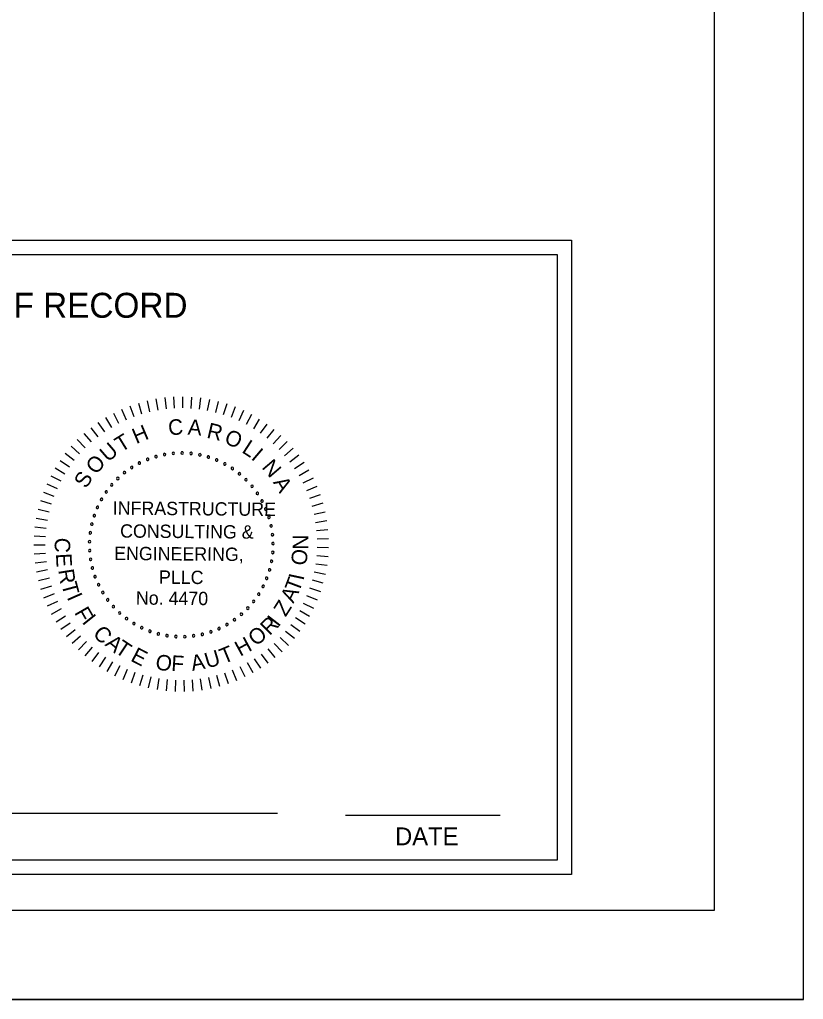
# Model space of a CAD drawing. Extents: x -1142 to 658, y -589 to 511.
# Drawn here: x 438.1 to 658.2, y -589.3 to -314.3 of the extents above; entities that cross this region are included whole.
import ezdxf

# ---------------------------------------------------------------- set-up
doc = ezdxf.new("R2010")
doc.units = 0
for name, color, linetype in [('BR_BORDER LINES', 7, 'Continuous'), ('BR_TEXT', 7, 'Continuous'), ('Default', 7, 'Continuous'), ('Level 31', 7, 'Continuous'), ('RD_SHT_IplotShp', 7, 'Continuous')]:
    doc.layers.add(name, color=color, linetype=linetype)

msp = doc.modelspace()

# ---------------------------------------------------------------- linework, layer by layer
at = {"layer": 'BR_BORDER LINES'}
for p, q in [((633.21, -564.26), (633.21, 485.67)), ((-1041.79, -564.26), (633.21, -564.26))]:
    msp.add_line(p, q, dxfattribs=at)
at = {"layer": 'BR_TEXT'}
for p, q in [((478.82, -420.42), (479.18, -423.58)), ((481.33, -420.21), (481.5, -423.39)), ((483.86, -420.16), (483.83, -423.34)), ((486.38, -420.26), (486.16, -423.44)), ((488.89, -420.51), (488.48, -423.67)), ((469.02, -422.76), (470.13, -425.74)), ((471.41, -421.95), (472.34, -425)), ((473.85, -421.29), (474.59, -424.39)), ((476.32, -420.78), (476.87, -423.91)), ((491.38, -420.92), (490.77, -424.05)), ((493.84, -421.48), (493.05, -424.56)), ((496.26, -422.19), (495.28, -425.22)), ((498.64, -423.04), (497.48, -426)), ((462.2, -426.04), (463.84, -428.77)), ((464.41, -424.81), (465.88, -427.63)), ((466.68, -423.71), (467.98, -426.62)), ((500.96, -424.04), (499.62, -426.92)), ((503.21, -425.17), (501.7, -427.97)), ((458.04, -428.89), (460, -431.4)), ((460.08, -427.4), (461.88, -430.02)), ((505.39, -426.45), (503.71, -429.15)), ((507.49, -427.85), (505.65, -430.44)), ((456.1, -430.5), (458.2, -432.88)), ((509.5, -429.38), (507.5, -431.85)), ((511.41, -431.02), (509.27, -433.37)), ((452.52, -434.06), (454.9, -436.17)), ((454.25, -432.22), (456.5, -434.48)), ((513.22, -432.78), (510.94, -435)), ((450.9, -436), (453.41, -437.96)), ((514.92, -434.65), (512.5, -436.72)), ((516.5, -436.62), (513.96, -438.54)), ((449.41, -438.03), (452.03, -439.84)), ((517.96, -438.68), (515.31, -440.44)), ((446.8, -442.35), (449.62, -443.82)), ((448.04, -440.15), (450.76, -441.79)), ((519.29, -440.83), (516.54, -442.42)), ((445.7, -444.62), (448.6, -445.92)), ((520.49, -443.05), (517.64, -444.47)), ((521.54, -445.34), (518.62, -446.59)), ((444.73, -446.95), (447.71, -448.07)), ((522.46, -447.69), (519.46, -448.76)), ((443.92, -449.34), (446.96, -450.28)), ((523.23, -450.09), (520.18, -450.98)), ((443.25, -451.78), (446.34, -452.52)), ((523.86, -452.54), (520.75, -453.24)), ((442.73, -454.25), (445.86, -454.8)), ((524.33, -455.02), (521.19, -455.53)), ((442.36, -456.74), (445.52, -457.11)), ((524.65, -457.52), (521.48, -457.84)), ((442.08, -461.78), (445.26, -461.76)), ((442.14, -459.26), (445.32, -459.43)), ((524.82, -460.04), (521.64, -460.16)), ((442.17, -464.3), (445.35, -464.09)), ((524.84, -462.57), (521.65, -462.49)), ((442.42, -466.82), (445.57, -466.41)), ((524.4, -467.59), (521.25, -467.13)), ((524.7, -465.09), (521.52, -464.82)), ((442.81, -469.31), (445.94, -468.71)), ((523.96, -470.08), (520.84, -469.43)), ((443.36, -471.77), (446.45, -470.98)), ((523.36, -472.53), (520.29, -471.69)), ((444.06, -474.2), (447.09, -473.22)), ((444.91, -476.58), (447.87, -475.42)), ((522.62, -474.94), (519.61, -473.92)), ((445.89, -478.9), (448.78, -477.56)), ((520.7, -479.61), (517.83, -478.22)), ((521.73, -477.31), (518.78, -476.1)), ((447.02, -481.16), (449.82, -479.65)), ((519.53, -481.85), (516.75, -480.29)), ((448.29, -483.34), (450.99, -481.66)), ((449.68, -485.45), (452.28, -483.61)), ((518.22, -484.01), (515.55, -482.28)), ((451.2, -487.46), (453.68, -485.47)), ((515.23, -488.07), (512.78, -486.03)), ((516.79, -486.08), (514.22, -484.2)), ((452.84, -489.38), (455.19, -487.24)), ((454.59, -491.2), (456.81, -488.91)), ((511.76, -491.74), (509.59, -489.42)), ((513.55, -489.96), (511.24, -487.77)), ((456.46, -492.9), (458.53, -490.49)), ((458.42, -494.49), (460.34, -491.95)), ((509.87, -493.41), (507.84, -490.96)), ((460.47, -495.95), (462.24, -493.31)), ((462.61, -497.29), (464.21, -494.54)), ((503.63, -497.68), (502.08, -494.9)), ((505.8, -496.38), (504.08, -493.71)), ((507.88, -494.96), (506, -492.39)), ((464.83, -498.5), (466.26, -495.65)), ((467.12, -499.56), (468.37, -496.64)), ((469.47, -500.49), (470.54, -497.49)), ((496.72, -500.75), (495.69, -497.73)), ((499.08, -499.87), (497.88, -496.92)), ((501.39, -498.84), (500.01, -495.98)), ((471.87, -501.27), (472.76, -498.21)), ((474.31, -501.9), (475.01, -498.8)), ((476.79, -502.39), (477.3, -499.24)), ((479.29, -502.72), (479.61, -499.55)), ((481.81, -502.9), (481.93, -499.71)), ((484.33, -502.92), (484.26, -499.74)), ((486.85, -502.79), (486.59, -499.62)), ((489.36, -502.51), (488.9, -499.36)), ((491.85, -502.07), (491.2, -498.95)), ((494.3, -501.48), (493.47, -498.41))]:
    msp.add_line(p, q, dxfattribs=at)
for centre, start, end in [((476.35, -436.97), 16.1422, 196.1422), ((476.35, -436.97), 196.1422, 16.1422), ((478.78, -436.4), 10.6038, 190.6038), ((478.78, -436.4), 190.6038, 10.6038), ((481.24, -436.06), 5.0653, 185.0653), ((481.24, -436.06), 185.0653, 5.0653), ((483.73, -435.97), 359.5268, 179.5268), ((483.73, -435.97), 179.5268, 359.5268), ((486.22, -436.11), 353.9884, 173.9884), ((486.22, -436.11), 173.9884, 353.9884), ((488.68, -436.5), 168.4499, 348.4499), ((488.68, -436.5), 348.4499, 168.4499), ((491.1, -437.12), 162.9114, 342.9114), ((491.1, -437.12), 342.9114, 162.9114), ((469.56, -440.04), 32.7576, 212.7576), ((469.56, -440.04), 212.7576, 32.7576), ((471.72, -438.8), 27.2191, 207.2191), ((471.72, -438.8), 207.2191, 27.2191), ((473.99, -437.77), 21.6807, 201.6807), ((473.99, -437.77), 201.6807, 21.6807), ((493.44, -437.97), 157.373, 337.373), ((493.44, -437.97), 337.373, 157.373), ((495.69, -439.04), 151.8345, 331.8345), ((495.69, -439.04), 331.8345, 151.8345), ((497.82, -440.33), 326.2961, 146.2961), ((467.53, -441.48), 38.2961, 218.2961), ((467.53, -441.48), 218.2961, 38.2961), ((497.82, -440.33), 146.2961, 326.2961), ((499.82, -441.81), 140.7576, 320.7576), ((499.82, -441.81), 320.7576, 140.7576), ((463.93, -444.92), 49.373, 229.373), ((463.93, -444.92), 229.373, 49.373), ((465.65, -443.12), 43.8345, 223.8345), ((465.65, -443.12), 223.8345, 43.8345), ((501.67, -443.48), 135.2191, 315.2191), ((501.67, -443.48), 315.2191, 135.2191), ((503.35, -445.33), 129.6807, 309.6807), ((503.35, -445.33), 309.6807, 129.6807), ((462.4, -446.89), 54.9114, 234.9114), ((462.4, -446.89), 234.9114, 54.9114), ((504.84, -447.32), 124.1422, 304.1422), ((504.84, -447.32), 304.1422, 124.1422), ((459.94, -451.21), 65.9884, 245.9884), ((459.94, -451.21), 245.9884, 65.9884), ((461.06, -448.99), 60.4499, 240.4499), ((461.06, -448.99), 240.4499, 60.4499), ((506.13, -449.45), 118.6038, 298.6038), ((506.13, -449.45), 298.6038, 118.6038), ((459.03, -453.53), 71.5268, 251.5268), ((459.03, -453.53), 251.5268, 71.5268), ((507.21, -451.7), 113.0653, 293.0653), ((507.21, -451.7), 293.0653, 113.0653), ((508.07, -454.03), 107.5268, 287.5268), ((508.07, -454.03), 287.5268, 107.5268), ((458.35, -455.93), 77.0653, 257.0653), ((458.35, -455.93), 257.0653, 77.0653), ((508.7, -456.44), 101.9884, 281.9884), ((508.7, -456.44), 281.9884, 101.9884), ((457.91, -458.38), 82.6038, 262.6038), ((457.91, -458.38), 262.6038, 82.6038), ((509.1, -458.91), 96.4499, 276.4499), ((509.1, -458.91), 276.4499, 96.4499), ((457.7, -460.86), 88.1422, 268.1422), ((457.7, -460.86), 268.1422, 88.1422), ((509.25, -461.39), 90.9114, 270.9114), ((509.25, -461.39), 270.9114, 90.9114), ((457.73, -463.36), 93.6807, 273.6807), ((457.73, -463.36), 273.6807, 93.6807), ((509.17, -463.88), 85.373, 265.373), ((509.17, -463.88), 265.373, 85.373), ((458.01, -465.83), 99.2191, 279.2191), ((458.01, -465.83), 279.2191, 99.2191), ((508.84, -466.35), 79.8345, 259.8345), ((508.84, -466.35), 259.8345, 79.8345), ((458.52, -468.27), 104.7576, 284.7576), ((458.52, -468.27), 284.7576, 104.7576), ((508.28, -468.78), 74.2961, 254.2961), ((508.28, -468.78), 254.2961, 74.2961), ((459.27, -470.65), 110.2961, 290.2961), ((459.27, -470.65), 290.2961, 110.2961), ((460.24, -472.94), 115.8345, 295.8345), ((460.24, -472.94), 295.8345, 115.8345), ((507.48, -471.14), 68.7576, 248.7576), ((507.48, -471.14), 248.7576, 68.7576), ((461.43, -475.13), 121.373, 301.373), ((461.43, -475.13), 301.373, 121.373), ((505.23, -475.58), 57.6807, 237.6807), ((505.23, -475.58), 237.6807, 57.6807), ((506.47, -473.41), 63.2191, 243.2191), ((506.47, -473.41), 243.2191, 63.2191), ((462.82, -477.2), 126.9114, 306.9114), ((462.82, -477.2), 306.9114, 126.9114), ((503.8, -477.62), 52.1422, 232.1422), ((503.8, -477.62), 232.1422, 52.1422), ((464.41, -479.12), 132.4499, 312.4499), ((464.41, -479.12), 312.4499, 132.4499), ((466.17, -480.88), 137.9884, 317.9884), ((466.17, -480.88), 317.9884, 137.9884), ((500.37, -481.23), 41.0653, 221.0653), ((500.37, -481.23), 221.0653, 41.0653), ((502.17, -479.5), 46.6038, 226.6038), ((502.17, -479.5), 226.6038, 46.6038), ((468.1, -482.46), 143.5268, 323.5268), ((468.1, -482.46), 323.5268, 143.5268), ((470.17, -483.84), 149.0653, 329.0653), ((470.17, -483.84), 329.0653, 149.0653), ((496.31, -484.11), 29.9884, 209.9884), ((496.31, -484.11), 209.9884, 29.9884), ((498.41, -482.77), 35.5268, 215.5268), ((498.41, -482.77), 215.5268, 35.5268), ((472.37, -485.02), 154.6038, 334.6038), ((472.37, -485.02), 334.6038, 154.6038), ((474.66, -485.99), 160.1422, 340.1422), ((474.66, -485.99), 340.1422, 160.1422), ((477.04, -486.72), 165.6807, 345.6807), ((477.04, -486.72), 345.6807, 165.6807), ((489.38, -486.85), 13.373, 193.373), ((491.78, -486.16), 18.9114, 198.9114), ((491.78, -486.16), 198.9114, 18.9114), ((494.1, -485.24), 24.4499, 204.4499), ((494.1, -485.24), 204.4499, 24.4499), ((479.48, -487.23), 171.2191, 351.2191), ((479.48, -487.23), 351.2191, 171.2191), ((481.96, -487.49), 356.7576, 176.7576), ((481.96, -487.49), 176.7576, 356.7576), ((484.45, -487.52), 2.2961, 182.2961), ((484.45, -487.52), 182.2961, 2.2961), ((486.93, -487.3), 7.8345, 187.8345), ((486.93, -487.3), 187.8345, 7.8345), ((489.38, -486.85), 193.373, 13.373)]:
    msp.add_arc(centre, 0.351, start, end, dxfattribs=at)
at = {"layer": 'Default'}
for p, q in [((371.83, -537.07), (510.46, -537.07)), ((529.57, -537.64), (573.05, -537.64))]:
    msp.add_line(p, q, dxfattribs=at)
for points in [[(275.07, -376.26), (593.07, -376.26), (593.07, -554.26), (275.07, -554.26)], [(279.07, -380.26), (589.07, -380.26), (589.07, -550.26), (279.07, -550.26)]]:
    msp.add_lwpolyline(points, close=True, dxfattribs=at)
at = {"layer": 'Level 31'}
msp.add_lwpolyline([(-1141.79, 510.67), (-1141.79, -589.33), (658.21, -589.33), (658.21, 510.67)], dxfattribs=at)
at = {"layer": 'RD_SHT_IplotShp'}
msp.add_line((-1141.79, -589.26), (658.21, -589.26), dxfattribs=at)

# ---------------------------------------------------------------- texts
at = {"layer": 'BR_TEXT'}
for s, height, rotation, p in [('H', 4.36, 22.7882, (470.82, -433.51)), ('C', 4.36, 4.7281, (479.96, -431.04)), ('A', 4.36, 355.6981, (485.18, -430.79)), ('R', 4.36, 346.6681, (490.4, -431.64)), ('T', 4.36, 31.8182, (466.57, -435.89)), ('O', 4.36, 337.638, (495.28, -433.13)), ('U', 4.36, 40.8482, (462.91, -438.7)), ('L', 4.36, 327.108, (500.23, -435.65)), ('O', 4.36, 49.8782, (459.56, -442.25)), ('I', 4.36, 319.578, (502.85, -437.54)), ('N', 4.36, 310.548, (505.89, -440.08)), ('S', 4.36, 58.9083, (456.79, -446.16)), ('A', 4.36, 301.5179, (509.15, -444.2)), ('INFRASTRUCTURE', 3.7386, 359.5268, (464.22, -453.28)), ('CONSULTING &', 3.7386, 359.5268, (466.28, -459.71)), ('C', 4.36, 267.025, (448.04, -459.65)), ('N', 4.36, 89.2085, (519.11, -463.14)), ('E', 4.36, 273.025, (448.26, -464.23)), ('ENGINEERING,', 3.7386, 359.5268, (464.61, -465.99)), ('O', 4.36, 83.2085, (518.56, -467.71)), ('R', 4.36, 279.025, (448.9, -468.85)), ('PLLC', 3.739, 359.5268, (477.19, -472.66)), ('I', 4.36, 77.9093, (517.78, -471.93)), ('T', 4.36, 285.025, (449.77, -472.79)), ('T', 4.36, 69.3954, (516.5, -475.3)), ('I', 4.36, 293.7713, (451.25, -476.44)), ('No. 4470', 3.739, 359.5268, (470.71, -478.51)), ('A', 4.36, 63.3954, (514.96, -478.32)), ('Z', 4.36, 57.3954, (512.77, -482.14)), ('F', 4.36, 299.7713, (453.31, -480.74)), ('I', 4.36, 308.5268, (455.42, -483.44)), ('R', 4.36, 44.5268, (508.24, -487.39)), ('I', 4.36, 52.3339, (510.71, -485.02)), ('C', 4.36, 314.5268, (458.39, -486.94)), ('O', 4.36, 38.5268, (504.41, -490.38)), ('A', 4.36, 320.5268, (461.84, -489.87)), ('T', 4.36, 326.5268, (464.57, -491.8)), ('H', 4.36, 28.5268, (500.01, -493.18)), ('E', 4.36, 332.5268, (468.99, -494.18)), ('U', 4.36, 16.5268, (490.76, -496.49)), ('T', 4.36, 22.5268, (495.35, -495.27)), ('O', 4.36, 350.5268, (476, -496.63)), ('F', 4.36, 356.5268, (480.57, -497.08)), ('A', 4.36, 10.5268, (486.57, -497.17))]:
    msp.add_text(s, height=height, rotation=rotation, dxfattribs=at).set_placement(p)
at = {"layer": 'Default'}
for s, height, p in [('ENGINEER OF RECORD', 7, (377.57, -398.01)), ('DATE', 5, (543.51, -546.06))]:
    msp.add_text(s, height=height, dxfattribs=at).set_placement(p)

doc.saveas('drawing.dxf')
